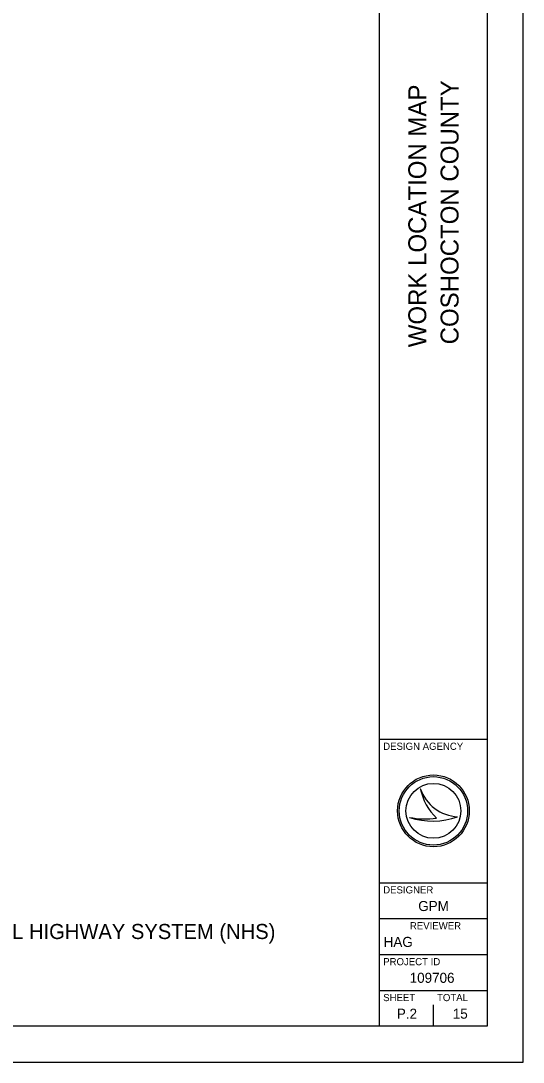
# Model space of a CAD drawing. Extents: x 2004415 to 2276415, y 751181 to 927181.
# Drawn here: x 2220435 to 2276415, y 751181 to 867212 of the extents above; entities that cross this region are included whole.
import ezdxf

# ---------------------------------------------------------------- set-up
doc = ezdxf.new("R2010")
doc.units = 0
for name, color, linetype in [('Default', 7, 'Continuous'), ('SH_Border', 7, 'Continuous'), ('SH_Cut_Line', 7, 'Continuous'), ('SH_Data', 7, 'Continuous')]:
    doc.layers.add(name, color=color, linetype=linetype)

msp = doc.modelspace()

# ---------------------------------------------------------------- linework, layer by layer
at = {"layer": 'SH_Border'}
for p, q in [((2260415, 755181), (2260415, 923181)), ((2260415, 787181), (2272415, 787181)), ((2260415, 771181), (2272415, 771181)), ((2260415, 767181), (2272415, 767181)), ((2260415, 763181), (2272415, 763181)), ((2260415, 759181), (2272415, 759181))]:
    msp.add_line(p, q, dxfattribs=at)
msp.add_lwpolyline([(2016415, 923181), (2272415, 923181), (2272415, 755181), (2016415, 755181)], close=True, dxfattribs=at)
at = {"layer": 'SH_Cut_Line'}
msp.add_lwpolyline([(2004415, 751181), (2276415, 751181), (2276415, 927181), (2004415, 927181)], close=True, dxfattribs=at)
at = {"layer": 'SH_Data'}
for p, q in [((2264955, 781657), (2264955, 781657)), ((2266415, 779181), (2266415, 779181)), ((2263753, 778457), (2263753, 778457)), ((2269114, 778529), (2269114, 778529)), ((2263415, 756581), (2263415, 756581)), ((2266415, 755181), (2266415, 757581))]:
    msp.add_line(p, q, dxfattribs=at)
for radius in [4000, 3814, 3814, 3058]:
    msp.add_circle((2266415, 779181), radius, dxfattribs=at)
for centre, radius, start, end in [((2269343, 783162), 4639, 198.92567, 198.93195), ((2271189, 782941), 6365, 191.63793, 191.64215), ((2269343, 783162), 4639, 198.93195, 267.16574), ((2271189, 782941), 6365, 191.64215, 226.09467), ((2266331, 786141), 8105, 251.45764, 290.08324), ((2265599, 788415), 10128, 259.49639, 259.49952), ((2266331, 786141), 8105, 251.45274, 251.45764), ((2265599, 788415), 10128, 259.49952, 276.66723)]:
    msp.add_arc(centre, radius, start, end, dxfattribs=at)

# ---------------------------------------------------------------- texts
at = {"layer": 'Default'}
msp.add_text('NATIONAL HIGHWAY SYSTEM (NHS)', height=1680, dxfattribs=at).set_placement((2209485, 764901))
at = {"layer": 'SH_Data'}
for s, p in [('WORK LOCATION MAP', (2265615, 830839)), ('COSHOCTON COUNTY', (2269215, 831166))]:
    msp.add_text(s, height=2000, rotation=90, dxfattribs=at).set_placement(p)
for s, height, p in [('DESIGN AGENCY', 800, (2260815, 785981)), ('DESIGNER', 800, (2260815, 769981)), ('GPM', 1120, (2264722, 768021)), ('REVIEWER', 800, (2263790, 765981)), ('HAG', 1120, (2260869, 764021)), ('PROJECT ID', 800, (2260815, 761981)), ('109706', 1120, (2263768, 760021)), ('SHEET', 800, (2260815, 757981)), ('TOTAL', 800, (2266815, 757981)), ('P.2', 1120, (2262339, 756021)), ('15', 1120, (2268573, 756021))]:
    msp.add_text(s, height=height, dxfattribs=at).set_placement(p)

doc.saveas('drawing.dxf')
